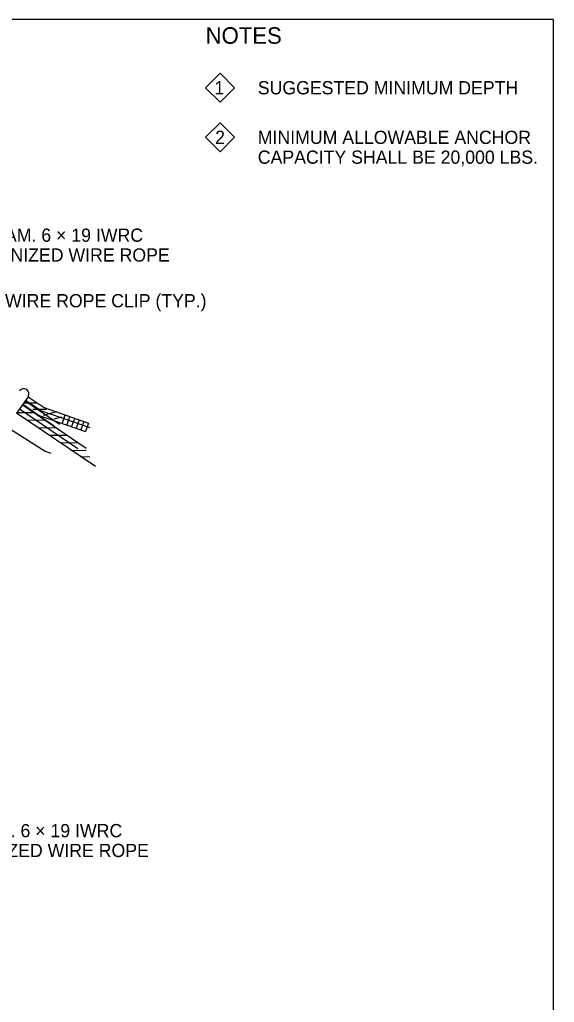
# Model space of a CAD drawing. Extents: x 99861 to 103151, y 100000 to 102076.
# Drawn here: x 102504 to 103151, y 100887 to 102076 of the extents above; entities that cross this region are included whole.
import ezdxf

# ---------------------------------------------------------------- set-up
doc = ezdxf.new("R2010")
doc.units = 0
for name, color, linetype in [('Level 1', 7, 'Continuous'), ('Level 18', 7, 'Continuous'), ('Level 2', 7, 'Continuous'), ('Level 20', 7, 'Continuous'), ('Level 28', 7, 'Continuous'), ('Level 4', 7, 'Continuous'), ('Level 60', 7, 'Continuous')]:
    doc.layers.add(name, color=color, linetype=linetype)

msp = doc.modelspace()

# ---------------------------------------------------------------- linework, layer by layer
at = {"layer": 'Level 1'}
for p, q in [((102511.9, 101607.4), (102545.4, 101584.8)), ((102587.5, 101587.7), (102584.1, 101577.8)), ((102587.5, 101587.7), (102584.1, 101577.8))]:
    msp.add_line(p, q, dxfattribs=at)
msp.add_lwpolyline([(99861, 100000), (103150, 100000), (103150, 102076), (99861, 102076)], close=True, dxfattribs=at)
for points in [[(102514.4, 101619.7), (102533.8, 101606.5), (102587.5, 101587.7)], [(102584.9, 101557.1), (102507.3, 101609.7)], [(102508.1, 101610.7), (102528, 101597.1), (102584.1, 101577.8)], [(102595.8, 101535.2), (102500.5, 101599.8)]]:
    msp.add_lwpolyline(points, dxfattribs=at)
at = {"layer": 'Level 2'}
msp.add_lwpolyline([(102109.6, 101851.4), (102143.6, 101827.1), (102169.6, 101815.9), (102185.3, 101796.3), (102239, 101755.4), (102275, 101728.8), (102305.4, 101711.9), (102328.8, 101696.3), (102371.7, 101667.9), (102391, 101654.8), (102398.4, 101648.9), (102449.8, 101608), (102535.3, 101553.7), (102542, 101551.4)], dxfattribs=at)
at = {"layer": 'Level 20'}
for points in [[(102746.7, 102011.2), (102764.3, 101993.6), (102746.7, 101976), (102729.2, 101993.6)], [(102746.7, 101951.2), (102764.3, 101933.6), (102746.7, 101916), (102729.2, 101933.6)]]:
    msp.add_lwpolyline(points, close=True, dxfattribs=at)
at = {"layer": 'Level 28'}
msp.add_line((102514.4, 101619.7), (102500.5, 101599.8), dxfattribs=at)
msp.add_arc((102509.3, 101623.2), 6.15, 325.2522, 145.2522, dxfattribs=at)
at = {"layer": 'Level 4'}
for p, q in [((102525.4, 101611.9), (102508.8, 101611.7)), ((102520.6, 101600.3), (102500.7, 101600)), ((102536.6, 101604.3), (102520, 101604.1)), ((102548.8, 101601.4), (102532.8, 101596.8)), ((102554.8, 101595), (102545.7, 101592.4)), ((102559, 101597.4), (102555.7, 101587.5)), ((102564.7, 101595.5), (102561.4, 101585.6)), ((102534.1, 101591.2), (102514.2, 101590.9)), ((102547.5, 101582.1), (102527.7, 101581.7)), ((102570.4, 101593.5), (102567, 101583.6)), ((102576.1, 101591.6), (102572.7, 101581.7)), ((102581.8, 101589.7), (102578.4, 101579.8)), ((102561, 101572.9), (102541.1, 101572.6)), ((102574.5, 101563.8), (102554.6, 101563.5)), ((102584.7, 101554.5), (102566.3, 101554.2)), ((102589.3, 101546.9), (102577.6, 101546.7))]:
    msp.add_line(p, q, dxfattribs=at)
for points in [[(102552.6, 101586.2), (102510.6, 101614.7)], [(102511.5, 101615.7), (102530.7, 101602.6), (102589.3, 101582.4)], [(102574.7, 101556.7), (102503.9, 101604.7)]]:
    msp.add_lwpolyline(points, dxfattribs=at)
at = {"layer": 'Level 60'}
msp.add_line((103151, 102075.5), (103151, 102075.5), dxfattribs=at)

# ---------------------------------------------------------------- texts
at = {"layer": 'Level 18'}
for s, p in [('SUGGESTED MINIMUM DEPTH', (102792.3, 101985.6)), ('MINIMUM ALLOWABLE ANCHOR ', (102792.3, 101925.6)), ('CAPACITY SHALL BE 20,000 LBS.', (102792.3, 101901.6))]:
    msp.add_text(s, height=16, dxfattribs=at).set_placement(p)
at = {"layer": 'Level 20'}
for s, height, p in [('NOTES', 20, (102729.2, 102046.8)), ('1', 16, (102739.8, 101985.6)), ('2', 16, (102740.7, 101925.6)), ('3/4" DIAM. 6 × 19 IWRC ', 16, (102421.8, 101807.2)), ('GALVANIZED WIRE ROPE', 16, (102421.8, 101783.2)), ('WIRE ROPE CLIP (TYP.)', 16, (102486.6, 101727.9)), ('3/4" DIAM. 6 × 19 IWRC ', 16, (102396.6, 101086.6)), ('GALVANIZED WIRE ROPE', 16, (102396.6, 101062.6))]:
    msp.add_text(s, height=height, dxfattribs=at).set_placement(p)

doc.saveas('drawing.dxf')
